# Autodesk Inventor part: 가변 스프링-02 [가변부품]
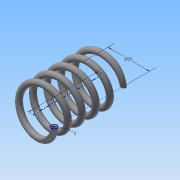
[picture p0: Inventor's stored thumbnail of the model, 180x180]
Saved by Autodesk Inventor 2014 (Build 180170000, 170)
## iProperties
Created: 2015-09
Part Number: 가변 스프링-02 [가변부품]
Material: 강철, 탄소
Document SubType Name: Modeling
Designer: study
Density: 7.87 g/cm^3
Appearance: 반연마
Mass: 18.9156 g
Surface Area: 32.5757 cm^2
Volume: 2.40351 cm^3
Author: study
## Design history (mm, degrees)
sketch "스케치1"
  geometry: L1 (0, 0)-(11, 0); L2 (11, 0)-(11, 39.945); L3 (11, 39.945)-(0, 39.945); L4 (0, 39.945)-(0, 0); C1 r 1.5 at (11, 0)
  constraints: 8 end point, 2 parallel, 1 centre point, 1 coincident, 1 horizontal, 1 perpendicular
  dimensions: "d0" = 22 diameter of L2.end L4; "d1" = 3 diameter of C1; "d2" = 39.9455 distance of L3.end L1.start (derived)
feature "코일1" sketch "스케치1" pitch "d3" = 10; turns "d5" = 5; dims "d4" = 39.9455 (= d2), "d6" = 0, angle "d7" = 90 deg, angle "d8" = 90 deg, "d9" = 0, "d10" = 0
node "작업 평면1"
sketch "스케치2"
  geometry: L1 (-12.5, 0)-(-9.5, 0) reference; 1 further point
  constraints: 1 horizontal alignment
extrude "돌출1" cut sketch "스케치2" stored distance "d12" = 10; taper "d13" = 0 deg
node "작업 평면2"
sketch "스케치3"
  geometry: L1 (-9.5, 0)-(-12.5, 0) reference; 1 further point
  constraints: 1 horizontal alignment
extrude "돌출2" cut sketch "스케치3" distance "d15" = 10; taper "d16" = 0 deg
node "솔리드1"
node "절단 모서리 투영1"
node "절단 모서리 투영2"
other parameters: "d11" = 0, "d14" = 39.9455 (= d2)
